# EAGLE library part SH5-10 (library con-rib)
RIBBON CABLE CONNECTOR Flachstecker / Faston
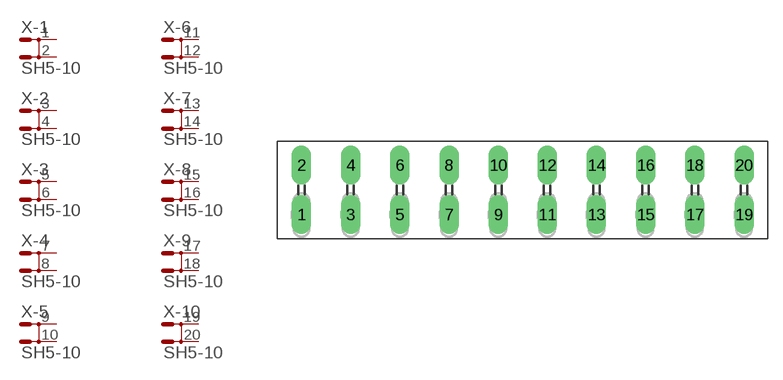
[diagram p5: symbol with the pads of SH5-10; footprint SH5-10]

Designator prefix X; gates -1=MD -2=MD -3=MD -4=MD -5=MD -6=MD -7=MD -8=MD -9=MD -10=MD

## SH5-10  [SH5-10]
1  -1:1  pas
2  -1:2  pas
3  -2:1  pas
4  -2:2  pas
5  -3:1  pas
6  -3:2  pas
7  -4:1  pas
8  -4:2  pas
9  -5:1  pas
10  -5:2  pas
11  -6:1  pas
12  -6:2  pas
13  -7:1  pas
14  -7:2  pas
15  -8:1  pas
16  -8:2  pas
17  -9:1  pas
18  -9:2  pas
19  -10:1  pas
20  -10:2  pas

## Footprint SH5-10 (pad centres in mm)
RIBBON CABLE CONNECTOR Flachstecker / Faston
drill 1.321 long: 1 -22.504,-2.515; 2 -22.504,2.515; 3 -17.501,-2.515; 4 -17.501,2.515; 5 -12.497,-2.515; 6 -12.497,2.515; 7 -7.493,-2.515; 8 -7.493,2.515; 9 -2.489,-2.515; 10 -2.489,2.515; 11 2.489,-2.515; 12 2.489,2.515; 13 7.493,-2.515; 14 7.493,2.515; 15 12.497,-2.515; 16 12.497,2.515; 17 17.501,-2.515; 18 17.501,2.515; 19 22.504,-2.515; 20 22.504,2.515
